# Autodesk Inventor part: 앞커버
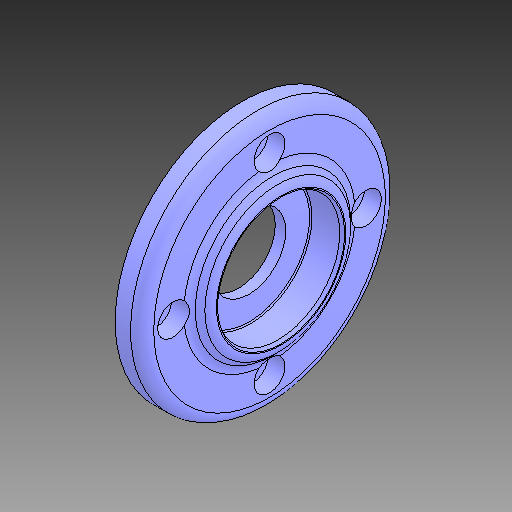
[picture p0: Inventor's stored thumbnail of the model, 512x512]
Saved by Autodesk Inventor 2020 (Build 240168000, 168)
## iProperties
Created: 2025-05
Part Number: 앞커버
Material: 알루미늄 6061
Document SubType Name: Modeling
Designer: CA01
Density: 2.7 g/cm^3
Appearance: 기본값
Author: jhkim
Sending System: Autodesk Inventor 2026
Preprocessor: ST-DEVELOPER v20.1
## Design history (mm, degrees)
feature "솔리드1"
node "솔리드2"
